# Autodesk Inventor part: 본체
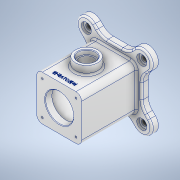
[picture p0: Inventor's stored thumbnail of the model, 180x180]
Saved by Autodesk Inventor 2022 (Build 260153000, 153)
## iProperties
Created: 2022-05
Part Number: 본체
Material: 알루미늄 6061
Document SubType Name: Modeling
Designer: Admin
Density: 2.7 g/cm^3
Appearance: 알루미늄 - 평지
Mass: 1070.77 g
Surface Area: 875.019 cm^2
Volume: 396.582 cm^3
Author: Admin
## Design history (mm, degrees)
sketch "스케치1"
  geometry: L1 (-40, 40)-(40, 40); L2 (40, 40)-(40, -40); L3 (40, -40)-(-40, -40); L4 (-40, -40)-(-40, 40); L5 (-40, 40)-(40, -40); L6 (40, 40)-(-40, -40); 1 further point
  constraints: 12 end point, 2 midpoint, 2 parallel, 1 horizontal, 1 perpendicular
  dimensions: "d0" = 80 distance of L1.end L2.end; "d1" = 80 distance of L1.start L1.end
extrude "돌출1" new body sketch "스케치1" distance "d2" = 98; taper "d3" = 0 deg
sketch "스케치2"
  geometry: L1 (-49, 49)-(49, 49); L2 (49, 49)-(49, -49); L3 (49, -49)-(-49, -49); L4 (-49, -49)-(-49, 49); L5 (-49, 49)-(49, -49); L6 (49, 49)-(-49, -49); L7 (36.272, 61.728)-(23.544, 49); L8 (61.728, 36.272)-(49, 23.544); L9 (-36.272, 61.728)-(-23.544, 49); L10 (-61.728, 36.272)-(-49, 23.544); L11 (-61.728, -36.272)-(-49, -23.544); L12 (-36.272, -61.728)-(-23.544, -49); L13 (61.728, -36.272)-(49, -23.544); L14 (36.272, -61.728)-(23.544, -49); A1 r 18 centre (49, 49) between (36.272, 61.728) and (61.728, 36.272); A2 r 18 centre (49, -49) between (61.728, -36.272) and (36.272, -61.728); A3 r 18 centre (-49, -49) between (-61.728, -36.272) and (-36.272, -61.728); A4 r 18 centre (-49, 49) between (-36.272, 61.728) and (-61.728, 36.272); 10 further points
  constraints: 28 end point, 8 point on circle, 7 point on line, 6 tangent, 5 parallel, 4 centre point, 4 coincident, 2 midpoint, 2 perpendicular, 1 horizontal
  dimensions: "d4" = 98 distance of L1.end L2.end; "d5" = 98 distance of L1.start L1.end; "d6" = 36 diameter of A4; "d7" = 36 diameter of A1; "d8" = 36 diameter of A2; "d9" = 36 diameter of A3
extrude "돌출2" join sketch "스케치2" distance "d10" = 12; taper "d11" = 0 deg
sketch "스케치3" dims "d81" = 140
  geometry: L1 (0, 0)-(-61.728, 61.728); C1 r 9 at (-49.497, 49.497); A1 r 18 centre (-49, 49) between (-36.272, 61.728) and (-61.728, 36.272) reference; 1 further point
  constraints: 2 end point, 1 centre point, 1 coincident, 1 point on circle, 1 point on line, 3 other
  dimensions: "d83" = 18 diameter of C1
extrude "돌출3" cut sketch "스케치3" distance "d14" = 4; taper "d15" = 0 deg
sketch "스케치4"
  geometry: C1 r 9 at (-0.497, 0.497) reference; C2 r 5 at (-0.497, 0.497); 2 further points
  constraints: 1 centre point, 1 coincident
  dimensions: "d84" = 10 diameter of C2
extrude "돌출4" cut sketch "스케치4" distance "d17" = 10; taper "d18" = 0 deg
sketch "스케치5"
  geometry: L1 (40, 0)-(-40, 0) reference; C1 r 20 at (0, 49); 1 further point
  constraints: 1 centre point
  dimensions: "d25" = 40 diameter of C1; "d26" = 49 distance from line of L1 C1.centre
extrude "돌출5" join sketch "스케치5" distance "d27" = 55; taper "d28" = 0 deg
sketch "스케치6"
  geometry: C1 r 20 at (0, 0) reference; C2 r 15 at (0, 0); 1 further point
  constraints: 1 centre point, 1 coincident
  dimensions: "d29" = 30 diameter of C2
extrude "돌출6" cut sketch "스케치6" distance "d30" = 8; taper "d31" = 0 deg
sketch "스케치7"
  geometry: C1 r 15 at (0, 0) reference; C2 r 12.5 at (0, 0); 1 further point
  constraints: 1 centre point, 1 coincident
  dimensions: "d32" = 25 diameter of C2
extrude "돌출7" cut sketch "스케치7" distance "d33" = 50; taper "d34" = 0 deg
sketch "스케치8"
  geometry: L1 (0, 125.252)-(0, -33.04); L2 (-40, 98)-(40, 98) reference; L3 (23.544, -12)-(-23.544, -12) reference; L4 (0, 98)-(25, 98); L5 (25, 98)-(25, 86); L6 (25, 86)-(0, 86); L7 (0, 86)-(0, 98); L8 (0, 86)-(35, 86); L9 (35, 86)-(35, 0); L10 (35, 0)-(0, 0); L11 (0, 0)-(0, 86); L12 (0, 0)-(25, 0); L13 (25, 0)-(25, -12); L14 (25, -12)-(0, -12); L15 (0, -12)-(0, 0); 12 further points
  constraints: 26 end point, 6 parallel, 3 horizontal, 3 perpendicular, 2 midpoint, 1 point on line, 1 vertical
  dimensions: "d35" = 50 diameter of L13 L1; "d36" = 50 diameter of L5 L1; "d37" = 70 diameter of L9 L1; "d38" = 12 distance of L4.end L5.end; "d70" = 12 distance of L12.end L13.end; "d71" = 86 distance of L8.end L9.end
revolve "회전1" sketch "스케치8" stored, may be unused: angle "d40" = 90 deg
sketch "스케치9"
  geometry: L1 (-30, 30)-(30, 30); L2 (30, 30)-(30, -30); L3 (30, -30)-(-30, -30); L4 (-30, -30)-(-30, 30); L5 (-30, 30)-(30, -30); L6 (30, 30)-(-30, -30); 5 further points
  constraints: 12 end point, 4 coincident, 2 midpoint, 2 parallel, 1 horizontal, 1 perpendicular
  dimensions: "d41" = 60 distance of L1.start L1.end; "d42" = 60 distance of L1.end L2.end
hole "구멍1" sketch "스케치9" at (-30, 30), (30, 30), (30, -30), (-30, -30) diameter "d43" = 3.242; stored, may be unused: countersink angle "d47" = 82 deg, drill point angle "d49" = 118 deg; dims "d44" = 8, "d45" = 3.023, "d46" = 2, "d48" = 10
fillet "모깎기2" dims "d50" = 10
fillet "모깎기3" dims "d51" = 3
chamfer "모따기1" distance "d53" = 1; stored, may be unused: second distance "d54" = 2, angle "d55" = 45 deg
chamfer "모따기2" distance "d56" = 1; stored, may be unused: second distance "d57" = 2, angle "d58" = 45 deg
fillet "모깎기5" dims "d59" = 3
sketch "스케치10"
  geometry: L1 (-30, 30)-(30, 30); L2 (30, 30)-(30, -30); L3 (30, -30)-(-30, -30); L4 (-30, -30)-(-30, 30); L5 (-30, 30)-(30, -30); L6 (30, 30)-(-30, -30); C1 r 1.621 at (-30, 30) reference; C2 r 1.621 at (30, 30) reference; C3 r 1.621 at (30, -30) reference; C4 r 1.621 at (-30, -30) reference; 5 further points
  constraints: 12 end point, 4 coincident, 2 midpoint, 2 parallel, 1 horizontal, 1 perpendicular
  dimensions: "d60" = 60 distance of L1.end L2.end; "d61" = 60 distance of L1.start L1.end
hole "구멍2" sketch "스케치10" at (-30, 30), (30, 30), (30, -30), (-30, -30) diameter "d62" = 3.242; stored, may be unused: countersink angle "d66" = 90 deg, drill point angle "d68" = 118 deg; dims "d63" = 8, "d64" = 4, "d65" = 2, "d67" = 10
fillet "모깎기6" dims "d69" = 3
fillet "모깎기8" dims "d79" = 25
fillet "모깎기9" dims "d80" = 3
sketch "스케치11" dims "d0" = 80, "d1" = 80
  geometry: L1 (70, 0)-(70, 95) reference; L2 (60, 0)-(0, 0) reference; 2 further points
  constraints: 1 other
  dimensions: "d88" = 40 distance from line of L1 point (30, 10); "d89" = 10 distance from line of L2 point (30, 10)
feature "엠보싱1" sketch "스케치11" dims "d0" = 80, "d1" = 80, "d90" = 0.5, "d91" = 0
node "솔리드1"
pattern_circular "원형 패턴1" dims angle "d86" = 360 deg
feature "A9D066F2-1C7D-4E18-AEED-F7BC21143FA4" dims "d62" = 3.242, "d63" = 8, "d64" = 4, "d65" = 2, "d66" = 90 deg, "d67" = 10, "d68" = 118 deg
